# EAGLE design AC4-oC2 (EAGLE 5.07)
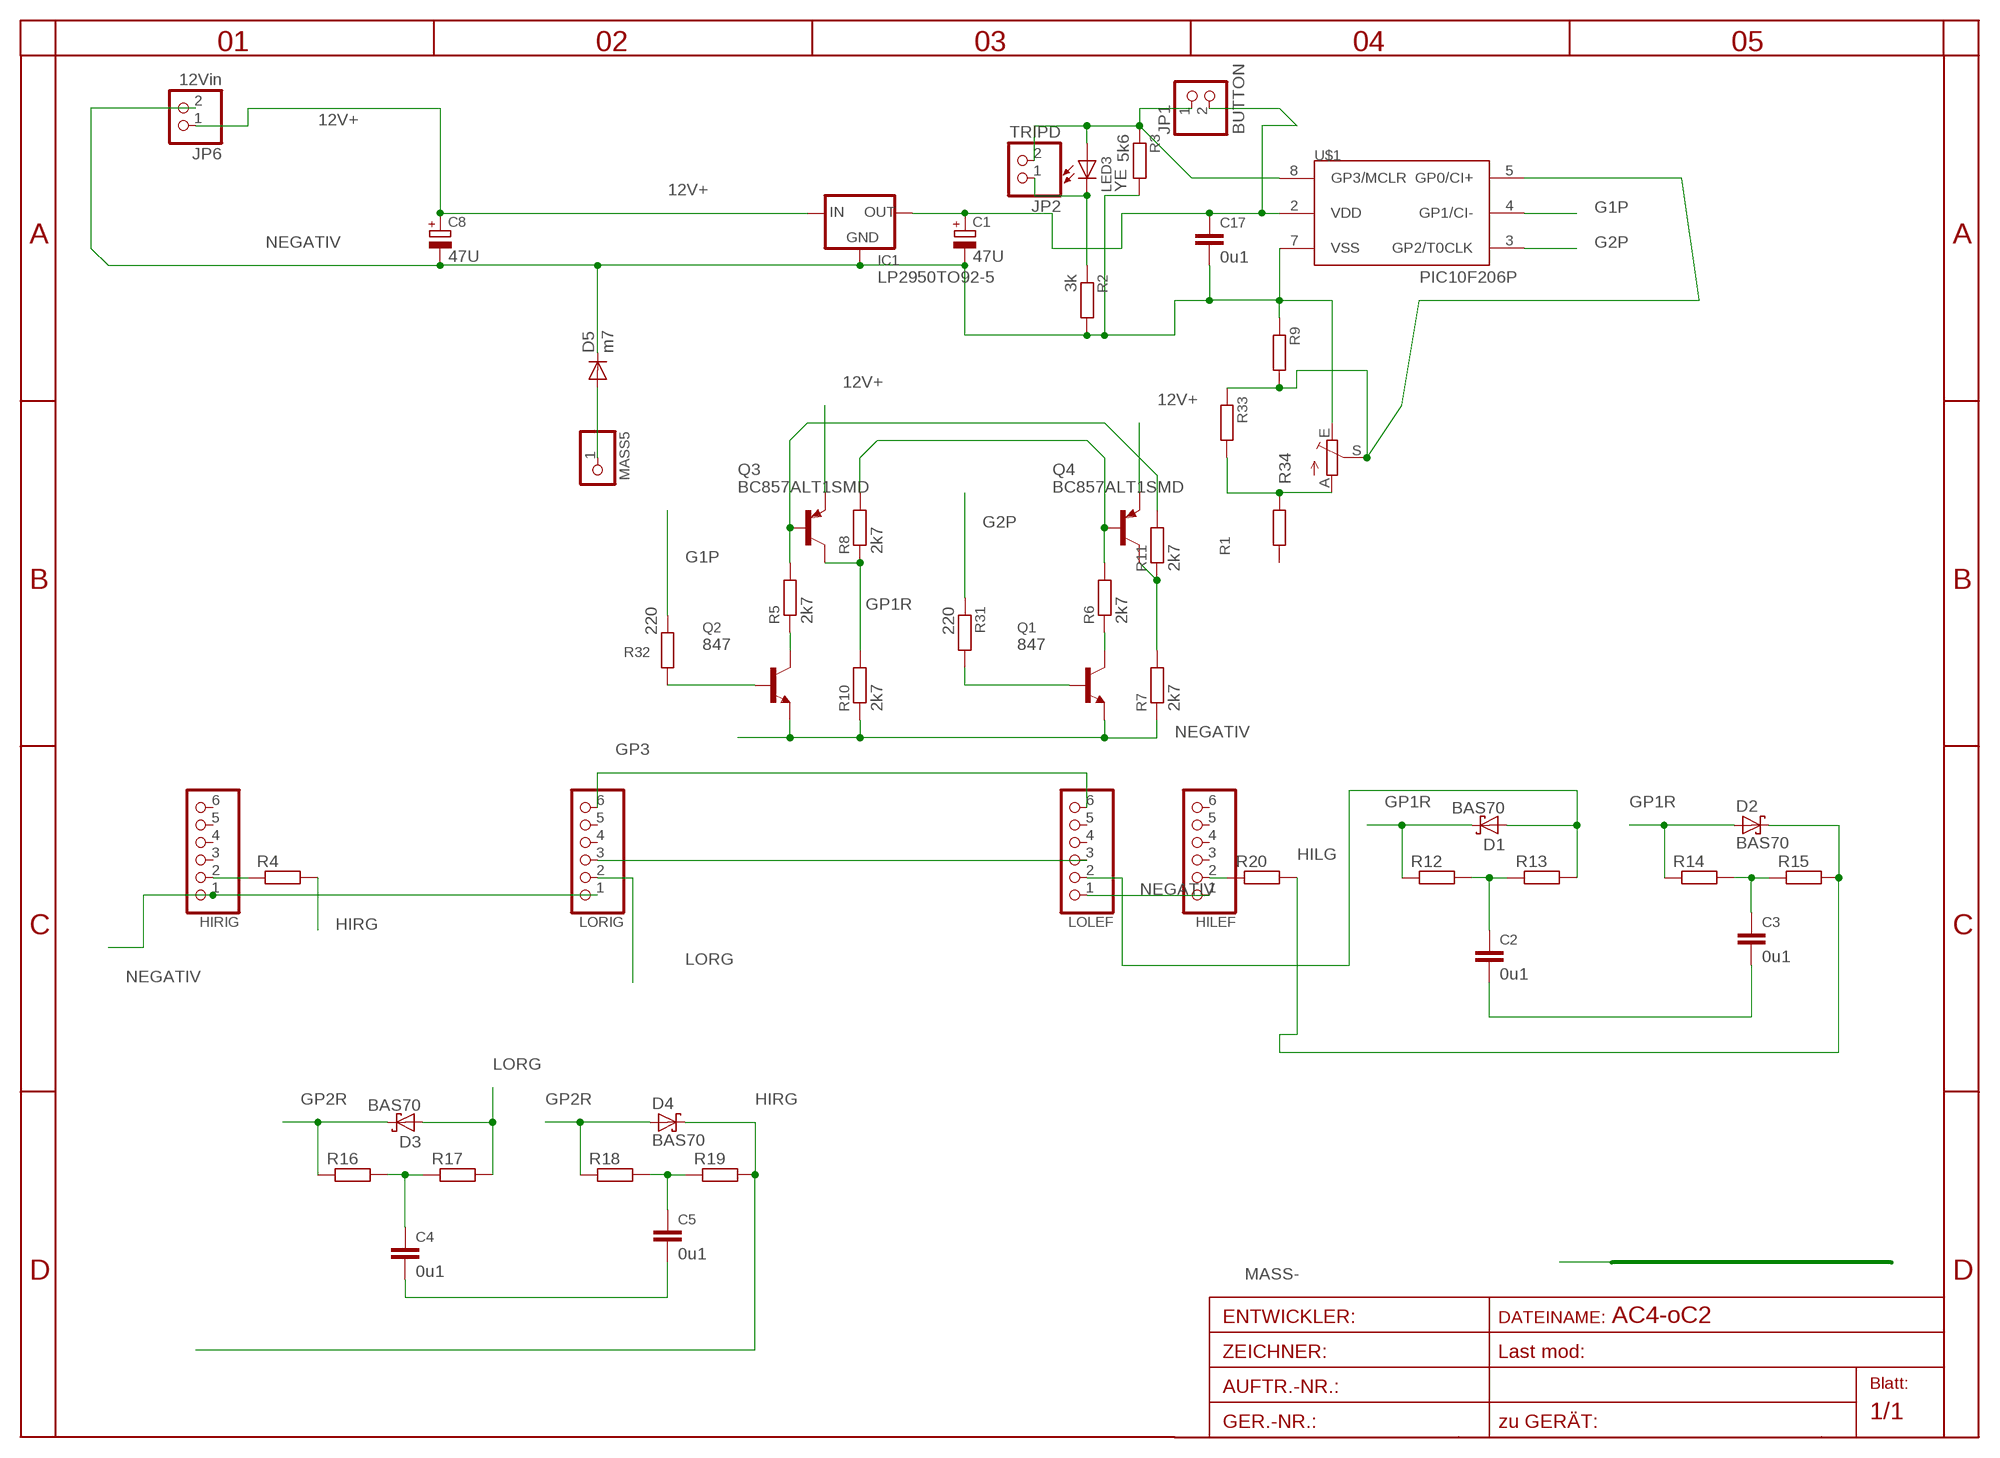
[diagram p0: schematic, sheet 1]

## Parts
C1  47U  CPOL-EUE5-6  [E5-6]
C2  0u1  C-EUC1206  [C1206]
C3  0u1  C-EUC1206  [C1206]
C4  0u1  C-EUC1206  [C1206]
C5  0u1  C-EUC1206  [C1206]
C8  47U  CPOL-EUE5-5  [E5-5]
C17  0u1  C-EUC1206  [C1206]
D1  BAS70  [SOT23]
D2  BAS70  [SOT23]
D3  BAS70  [SOT23]
D4  BAS70  [SOT23]
D5  m7  DIODE-SMA-DO214  [SMA-DO214AC]
HILEF  PINHD-1X6  [1X06BOX]
HIRIG  PINHD-1X6  [1X06BOX]
IC1  LP2950TO92-5  [T092-5]
JP1  BUTTON  PINHD-1X2/90  [1X02/90]
JP2  TRIPD  PINHD-1X2/90  [1X02/90]
JP6  12Vin  PINHD-1X2STR  [1X02]
LED3  YE  LEDCHIPLED_1206  [CHIPLED_1206]
LOLEF  PINHD-1X6  [1X06BOX]
LORIG  PINHD-1X6  [1X06BOX]
MASS5  PINHD-1X11MM6  [1X1MM8]
Q1  847  BC847ALT1SMD  [SOT23]
Q2  847  BC847ALT1SMD  [SOT23]
Q3  BC857ALT1SMD  [SOT23-BEC]
Q4  BC857ALT1SMD  [SOT23-BEC]
R1  R-EU_0207/35  [0207/35]
R2  3k  R-EU_R0805  [R0805]
R3  5k6  R-EU_R0805  [R0805]
R4  R-EU_R0805  [R0805]
R5  2k7  R-EU_R0805  [R0805]
R6  2k7  R-EU_R0805  [R0805]
R7  2k7  R-EU_R0805  [R0805]
R8  2k7  R-EU_R0805  [R0805]
R9  R-EU_R0805  [R0805]
R10  2k7  R-EU_R0805  [R0805]
R11  2k7  R-EU_R0805  [R0805]
R12  R-EU_R0805  [R0805]
R13  R-EU_R0805  [R0805]
R14  R-EU_R0805  [R0805]
R15  R-EU_R0805  [R0805]
R16  R-EU_M0805  [M0805]
R17  R-EU_M0805  [M0805]
R18  R-EU_M0805  [M0805]
R19  R-EU_M0805  [M0805]
R20  R-EU_R0805  [R0805]
R31  220  R-EU_R1206  [R1206]
R32  220  R-EU_R1206  [R1206]
R33  R-EU_R0805  [R0805]
R34  TRIM_EU-S64W  [S64W]
U$1  PIC10F206P  [DIL8]

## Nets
12V+: C8.+ IC1.3(IN) JP6.1 LOLEF.3 LORIG.3 Q3.E Q4.E
G1P: R32.1 U$1.4(GP1/CI-)
G2P: R31.1 U$1.3(GP2/T0CLK)
GP1R: D1.3(C) D2.1(A) Q3.C R8.1 R10.2 R12.1 R14.1
GP2R: D3.3(C) D4.1(A) Q4.C R7.2 R11.1 R16.1 R18.1
GP3: JP1.1 JP2.2 LED3.A LOLEF.6 LORIG.6 R3.1 U$1.8(GP3/MCLR)
HILG: D2.3(C) R15.2 R20.2
HIRG: D4.3(C) R4.2 R19.2
LORG: D3.1(A) LORIG.2 R17.2
N$1: R9.2 R33.1 R34.S U$1.5(GP0/CI+)
N$2: Q2.1(B) R32.2
N$3: C3.1 R14.2 R15.1
N$4: Q2.3(C) R5.1
N$5: Q3.B R5.2 R11.2
N$6: Q1.1(B) R31.2
N$7: D5.A MASS5.1
N$8: C5.1 R18.2 R19.1
N$9: Q4.B R6.2 R8.2
N$11: Q1.3(C) R6.1
N$12: C2.1 R12.2 R13.1
N$13: HIRIG.2 R4.1
N$14: D1.1(A) LOLEF.2 R13.2
N$15: JP2.1 LED3.C R2.1
N$16: C4.1 R16.2 R17.1
N$17: HILEF.2 R20.1
N$42: R1.1 R33.2 R34.A
NEGATIV: C1.- C2.2 C3.2 C4.2 C5.2 C8.- C17.2 D5.K(C) HILEF.1 HIRIG.1 IC1.2(GND) JP6.2 LOLEF.1 LORIG.1 Q1.2(E) Q2.2(E) R2.2 R3.2 R7.1 R9.1 R10.1 R34.E U$1.7(VSS)
VDD: C1.+ C17.1 IC1.1(OUT) JP1.2 U$1.2(VDD)
Unconnected: HILEF.3 HILEF.4 HILEF.5 HILEF.6 HIRIG.3 HIRIG.4 HIRIG.5 HIRIG.6 LOLEF.4 LOLEF.5 LORIG.4 LORIG.5 R1.2

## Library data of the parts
C1 C8 = rcl-2:CPOL-EU: POLARIZED CAPACITOR, European symbol
C2-C5 C17 = rcl-2:C-EU: CAPACITOR, European symbol
D1-D4 = diode:BAS70: Silicon Schottky Diodes
D5 = diode:DIODE-: DIODE
HILEF HIRIG LOLEF LORIG = pinhead:PINHD-1X6: PIN HEADER
IC1 = v-reg:LP2950?*: Source: http://cache.national.com/ds/LP/LP2950.pdf
JP1 JP2 JP6 = pinhead:PINHD-1X2: PIN HEADER
LED3 = led:LED: LED
MASS5 = pinhead:PINHD-1X1: PIN HEADER
Q1 Q2 = transistor-npn:BC847*: NPN Transistor
Q3 Q4 = transistor-pnp:BC857*: PNP Transistror
R1-R3 R5-R11 R31-R33 = rcl-2:R-EU_: RESISTOR, European symbol
R4 R12-R20 = rcl:R-EU_: RESISTOR, European symbol
R34 = pot:TRIM_EU-: POTENTIOMETER
U$1 = microchip-5:PIC10F2*: uPC nW 0,25/0,5k Program Flash memory Comparator

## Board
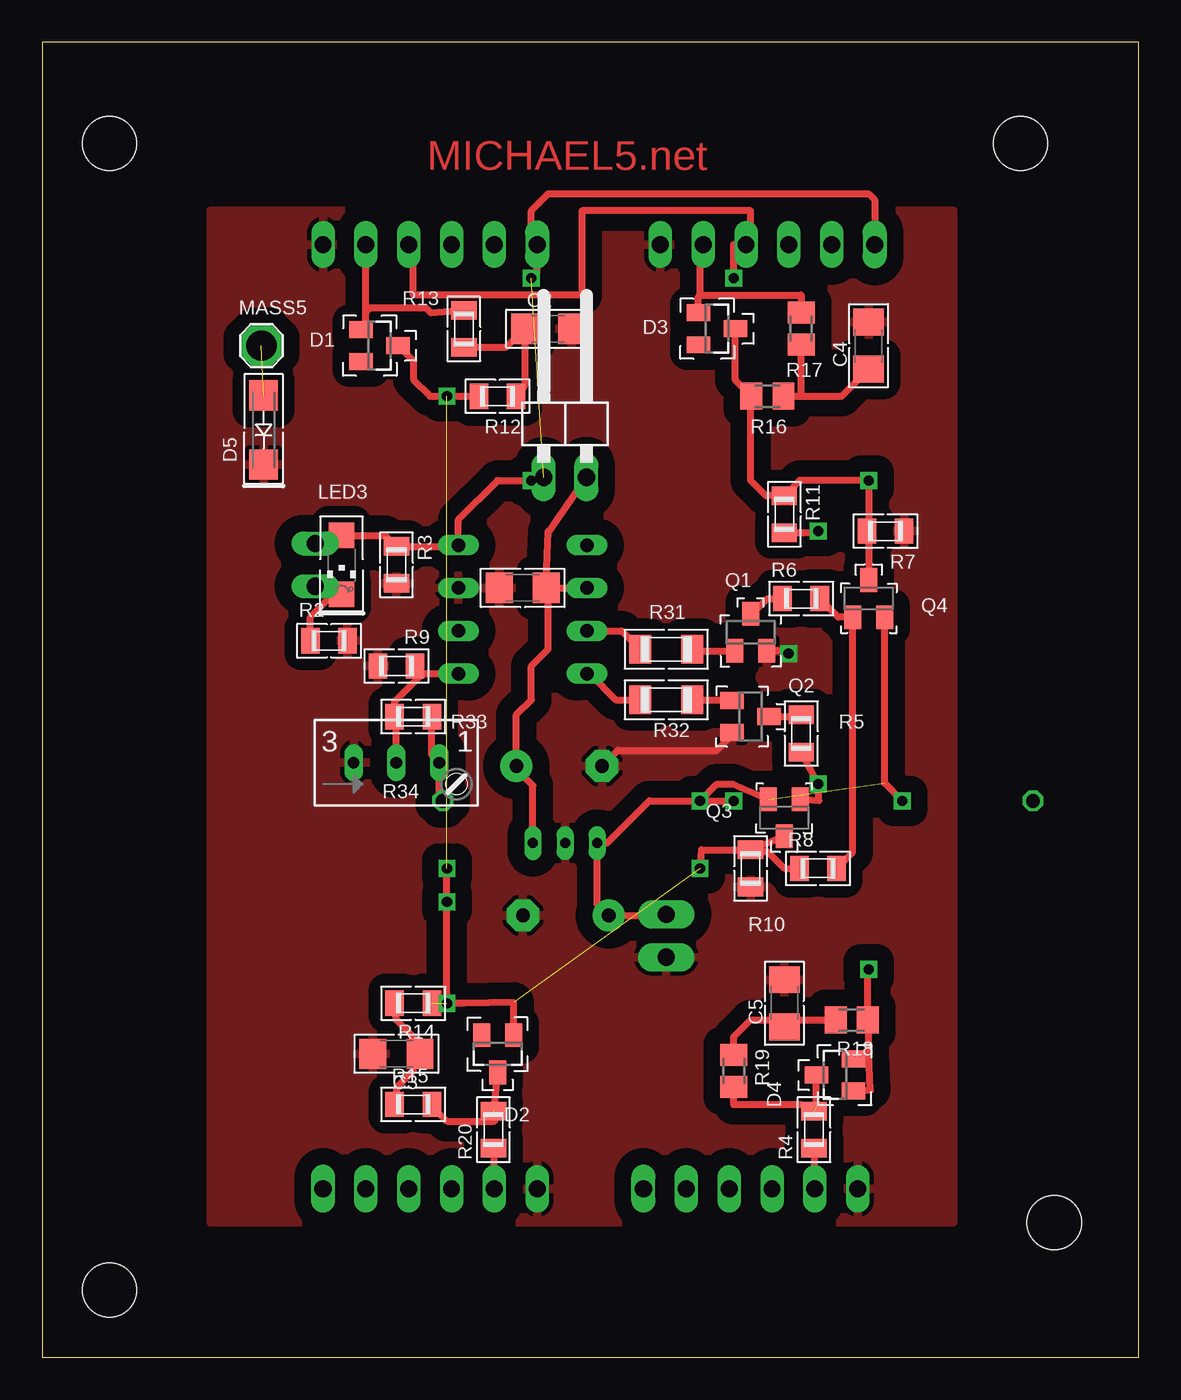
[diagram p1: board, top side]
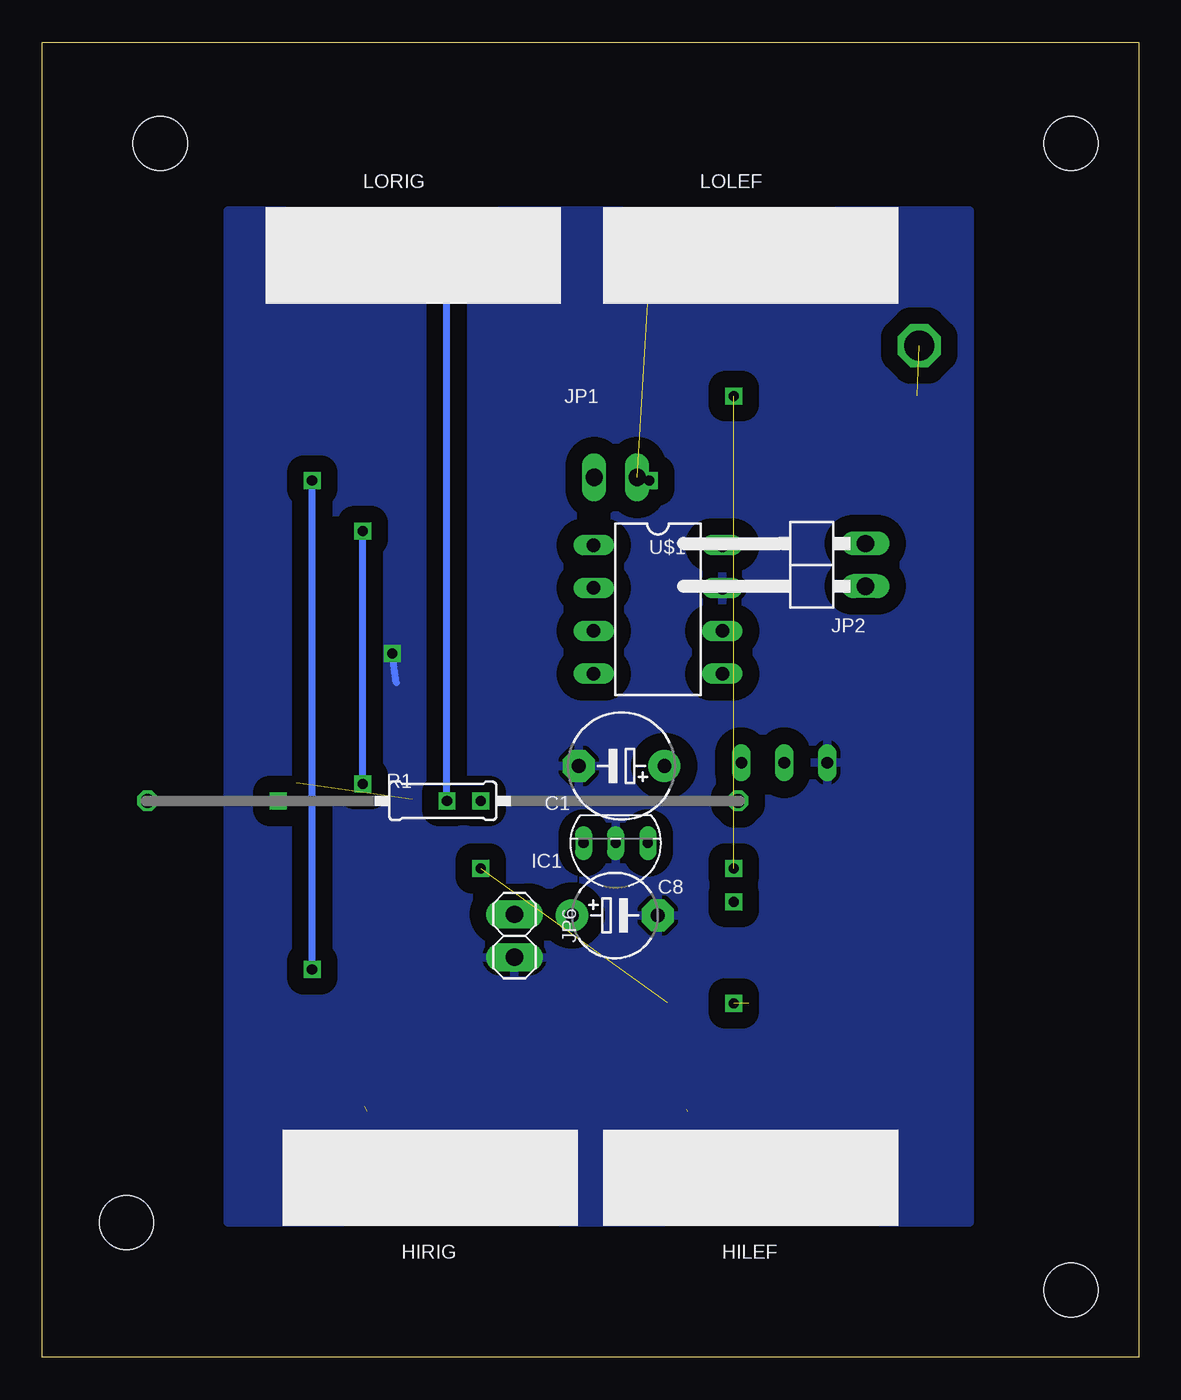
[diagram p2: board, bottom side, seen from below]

Size 65 x 78 mm. Coordinates in mm from the lower left corner, seen from the top.
Outline: 0,0 65,0 65,78 0,78 0,0
Copper layers (1*16): Top 0.035mm / dielectric 1.5mm / Bottom 0.035mm
Design rules "default *": minimum track width 12mil, minimum drill 24mil, track to track 8mil, track to pad 8mil, pad to pad 8mil, via to via 8mil, smd to smd 8mil, copper to edge 40mil, drill to drill 8mil, minimum pad ring 8mil, minimum via ring 8mil, stop-mask expansion 4mil, vias tented up to drill 0mil, thermal gap 10mil
Holes 3.2 mm at 4,72 4,4 58,72 60,8

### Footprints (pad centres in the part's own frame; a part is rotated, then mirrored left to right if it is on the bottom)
E5-6 = drill 0.813 pad 1.905 round: + -2.54,0 | drill 0.813 pad 1.905 octagon: - 2.54,0
C1206 = smd 1.6 x 1.8: 1 -1.4,0; 2 1.4,0
E5-5 = drill 0.813 pad 1.905 round: + -2.54,0 | drill 0.813 pad 1.905 octagon: - 2.54,0
SOT23 = smd 1 x 1.4: 1 -0.95,-1.1; 2 0.95,-1.1; 3 0,1.1
SMA-DO214AC = smd 1.8 x 1.7: A 2.05,-0.127; K -2.05,-0.127
1X06BOX = drill 1 long: 1 -6.35,0; 2 -3.81,0; 3 -1.27,0; 4 1.27,0; 5 3.81,0 | drill 1.016 long: 6 6.35,0
T092-5 = drill 0.6 pad 0.813 long: 1 -1.905,0; 2 0,0; 3 1.905,0
1X02/90 = drill 1.016 long: 1 -1.27,-3.81; 2 1.27,-3.81
1X02 = drill 1.016 pad 1.676 long: 1 -1.27,0; 2 1.27,0
CHIPLED_1206 = smd 1.5 x 1.5: A 0,-1.75; C 0,1.75
1X1MM8 = drill 1.8 pad 2.54 octagon: 1 0,0
SOT23-BEC = smd 1 x 1.4: B -0.95,-1.1; C 0,1.1; E 0.95,-1.1
0207/35 = drill 0.813 octagon: 1 -17.5,0; 2 17.5,0
R0805 = smd 1.1 x 1.5: 1 -1.1,0; 2 1.1,0
M0805 = smd 1.3 x 1.6: 1 -0.95,0; 2 0.95,0
R1206 = smd 1.3 x 1.7: 1 -1.55,0; 2 1.55,0
S64W = drill 0.7 long: A 2.54,1.27; E -2.54,1.27; S 0,1.27
DIL8 = drill 0.8 long: 1 -3.81,-3.81; 2 -1.27,-3.81; 3 1.27,-3.81; 4 3.81,-3.81; 5 3.81,3.81; 6 1.27,3.81; 7 -1.27,3.81; 8 -3.81,3.81

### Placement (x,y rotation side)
C1  30.65,35.07 180 bottom
C2  30,61 0 top
C3  21,18 180 top
C4  49,60 90 top
C5  44,21 90 top
C8  31.05,26.2 0 bottom
C17  28.49,45.63 180 top
D1  20,60 270 top
D2  27,18 180 top
D3  40,61 270 top
D4  47,16.75 90 top
D5  13,55 90 top
HILEF  23,10 0 bottom
HIRIG  42,10 0 bottom
IC1  31,30.5 180 bottom
JP1  31,56 0 top
JP2  20,47 90 bottom
JP6  37,25 270 bottom
LED3  17.75,47 180 top
LOLEF  23,66 180 bottom
LORIG  43,66 180 bottom
MASS5  13,60 0 top
Q1  42,43 0 top
Q2  42,38 270 top
Q3  44,32 180 top
Q4  49,45 0 top
R1  41.25,33 180 bottom
R2  17,42.5 0 top
R3  21,47 270 top
R4  45.75,13.5 90 top
R5  45,37 270 top
R6  45,45 0 top
R7  50,49 180 top
R8  46,29 0 top
R9  21,41 0 top
R10  42,29 90 top
R11  44,50 270 top
R12  27,57 0 top
R13  25,61 90 top
R14  22,21 180 top
R15  22,15 0 top
R16  43,57 0 top
R17  45,61 90 top
R18  48,20 180 top
R19  41,17 270 top
R20  26.75,13.5 90 top
R31  37,42 0 top
R32  37,39 0 top
R33  22,38 0 top
R34  21,34 0 top
U$1  28.49,44.36 270 bottom

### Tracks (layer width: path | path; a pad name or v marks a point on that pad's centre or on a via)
12V+  (via drill 0.6)  (1 unrouted)
  Top 0.406: Q4.E 49.95,34.05 v51,33 | v39,33 40,34 40.95,34 Q3.E | v39,33 36,33 33.5,30.5 IC1.3 32.91,26.89 C8.+ 36.94,26.2 JP6.1 | v41,64 41,66 LORIG.3 42,66 42,68 32,68 32,63 22,63 22,66 LOLEF.3 | v39,33 v41,33
  Bottom 0.406: v41,33 v41,64
G1P
  Top 0.406: U$1.4 32.45,40.55 34,39 R32.1
G2P
  Top 0.406: U$1.3 34.36,43.09 R31.1
GP1R  (via drill 0.6)  (3 unrouted)
  Top 0.406: D2.1 27.95,21.05 25,21 v24,21 v24,27 v24,29 | D1.3 22,59.1 22,58 23,57 v24,57 R12.1 | R10.2 39.1,30.1 v39,29 | R8.1 44,29 43,30 42.1,30 R10.2 | R10.2 Q3.C
GP2R  (via drill 0.6)
  Top 0.406: D3.3 41.1,57.95 R16.1 42,56.95 42,52 42.9,51.1 R11.1 44.9,52 v49,52 49,49.1 R7.2 49,48.9 Q4.C | v49,23 48.95,22.95 R18.1 49,19.95 49,18 49.1,15.85 D4.1
  Bottom 0.406: v49,23 v49,52
GP3  (via drill 0.6)  (1 unrouted)
  Top 0.406: v29,64 29.35,64.35 LOLEF.6 29,66.35 29,68 30,69 49,69 49.35,68.65 LORIG.6 | JP1.1 29.54,52 v29,52 27,52 24.68,49.68 U$1.8 24.61,48.1 R3.1 20.35,48.75 LED3.A 17.27,48.27 JP2.2
HILG  (1 unrouted)
  Top 0.406: D2.3 26.81,14.71 26.81,14 24,14 23,15 R15.2
HIRG  (1 unrouted)
  Top 0.406: D4.3 45.9,14.9 45,15 41,15 R19.2
LORG
  Top 0.406: D3.1 38.9,62.9 39,63 | 39,63 39,65.81 LORIG.2 | R17.2 45,63 39,63
N$1
  Top 0.406: R34.S 21,37.9 R33.1 20.9,38.9 22.55,40.55 | 22.55,40.55 U$1.5 | 22.55,40.55 R9.2
N$2
  Top 0.406: R32.2 40.85,39 Q2.1
N$3
  Top 0.406: R15.1 21.05,16.05 22,17 22,17.6 C3.1 22.4,18.6 21,20 21,20.05 R14.2
N$4
  Top 0.406: Q2.3 44.9,38 R5.1
N$5  (via drill 0.6)
  Top 0.406: R5.2 v46,34 46.05,33 Q3.B | R11.2 45.9,48.9 v46,49
  Bottom 0.406: v46,34 v46,49
N$6
  Top 0.406: Q1.1 38.65,41.9 R31.2
N$7  (1 unrouted)
N$8
  Top 0.406: R18.2 44.4,20 C5.1 43.6,20 42,20 41,19 R19.1
N$9
  Top 0.406: R8.2 48.05,29.95 Q4.B 47.2,43.9 R6.2
N$11
  Top 0.406: Q1.3 42.1,44.1 43,45 R6.1
N$12
  Top 0.406: R13.1 27.5,59.9 C2.1 28.6,57.65 R12.2
N$13
  Top 0.406: R4.1 45.81,12.4 HIRIG.2
N$14
  Top 0.406: 19.19,62 19.19,61.24 D1.1 | 19.19,62 LOLEF.2 | R13.2 23.05,61.95 22.75,62.25 19.44,62.25 19.19,62
N$15
  Top 0.406: R2.1 15.9,43.9 17,45 17.5,45 LED3.C 17.27,45.73 JP2.1
N$16
  Top 0.406: R16.2 45,57 | 45,57 47.4,57 C4.1 | 45,57 R17.1
N$17
  Top 0.406: R20.1 26.81,12.4 HILEF.2
N$42
  Top 0.406: R33.2 23.1,35.71 R34.A 23.54,33.21 R1.1
NEGATIV  (via drill 0.6)
  Top 0.406: Q2.2 40.9,36.9 40,36 34.12,36 C1.- | Q1.2 44.1,41.9 v44.25,41.75
  Bottom 0.406: 44,40 v44.25,41.75
  pour Top (isolate 1): 10,68 54,68 54,8 10,8
  pour Bottom (isolate 1): 10,68 54,68 54,8 10,8
VDD
  Top 0.406: C17.1 U$1.2 | C17.1 29.89,46.11 30,49 30,48.92 JP1.2 | IC1.1 29.09,33.91 28,35 28.05,35 C1.+ 28.11,38.11 29,39 29,41 30,42 30,45.52 C17.1

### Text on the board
Top: MICHAEL5.net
